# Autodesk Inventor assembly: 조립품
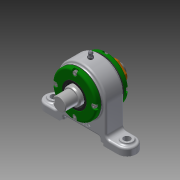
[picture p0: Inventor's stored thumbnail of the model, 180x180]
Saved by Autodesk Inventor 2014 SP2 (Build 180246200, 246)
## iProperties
Created: 2019-05
Part Number: 조립품
Document SubType Name: Assembly
Designer: gs
Author: gs
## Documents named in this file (13)
- C:\Users\gs\Desktop\490504V1042\조립품.iam
- C:\Users\gs\Desktop\490504V1042\본체.ipt
- C:\Users\gs\Desktop\490504V1042\커버.ipt
- C:\Users\gs\Desktop\490504V1042\축.ipt
- C:\Users\gs\Desktop\490504V1042\앵귤러 볼 베어링 7205.ipt
- C:\Users\gs\Desktop\490504V1042\오일 실 28 40 5 B.ipt
- C:\Users\gs\Desktop\490504V1042\개스킷.ipt
- C:\Users\gs\Desktop\490504V1042\그리스니플개스킷.ipt
- C:\Users\gs\Desktop\490504V1042\그리스니플 M6.ipt
- 그리스니플  M6.ipt
- C:\Users\gs\Desktop\490504V1042\볼트 M4.ipt
- C:\Users\gs\Desktop\490504V1042\베어링너트.ipt
- C:\Users\gs\Desktop\490504V1042\칼라.ipt
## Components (4 placed, 3 different names)
1. 개스킷:1
2. 개스킷:2
3. 그리스니플개스킷:1
4. 그리스니플  M6:1
